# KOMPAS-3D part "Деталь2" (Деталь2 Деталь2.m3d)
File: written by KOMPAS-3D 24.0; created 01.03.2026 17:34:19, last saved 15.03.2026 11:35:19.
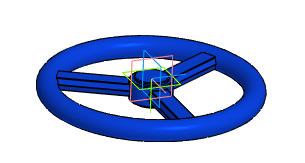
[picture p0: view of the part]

Document properties: Автор: R2D2; Полное имя файла: E:\Работа\Зайцев\GVWR2626M-2W-F-S Задвижка клиновая с выдвижным штоком DN.ru Ду50-300 Ру16\DN50\исходные материалы\Деталь2 Деталь2.m3d

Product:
- Body: Твердое тело1  | qty 1
    Масса: 3.95529
- Part/product: Деталь2
    Масса: 3.95529
    additional columns: Типовые

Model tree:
1. Твердое тело1  (labels: Твердое тело1)
2. Эскиз:1
3. Элемент выдавливания:1
     Расстояние 1 = 100
4. Эскиз:2
5. Элемент вращения:1
     Угол 1 = 360
6. Элемент выдавливания:2  (with: Грань.Элемент выдавливания:1)
     Расстояние 2 = 40
7. Массив по концентрической сетке:1  (with: Элемент выдавливания:2)  (labels: Грань.Твердое тело1)  (3 pattern instances)
     Шаг 2 = 360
